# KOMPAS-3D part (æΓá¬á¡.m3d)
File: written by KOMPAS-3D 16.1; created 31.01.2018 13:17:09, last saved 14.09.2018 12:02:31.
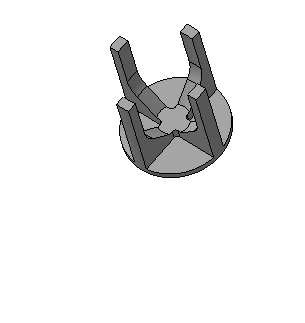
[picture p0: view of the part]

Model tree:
1. Эскиз:1
2. Операция вращения:1
     Угол 1 = 360
3. Эскиз:4
4. Операция выдавливания:3
     Расстояние 1 = 3.5; Расстояние 2 = 160
5. Эскиз:3
6. Вырезать элемент выдавливания:1
7. Массив по концентрической сетке:2  (with: Вырезать элемент выдавливания:1, Эскиз:3)  (4 pattern instances)
     Геометрический массив = 3; Шаг 2 = 360
8. Эскиз:5
9. Вырезать элемент выдавливания:2
     Расстояние 1 = 2
10. Фаска:1
     Угол = 45; Длина 1 = 1; Длина 2 = 1
11. Скругление:1
     Радиус = 15
12. Эскиз:8
13. Операция выдавливания:4
     Расстояние 1 = 10; Расстояние 2 = 6
14. Эскиз:9
15. Операция выдавливания:5
     Расстояние 1 = 3.5
16. Скругление:2
     Радиус = 2
17. Эскиз:7
18. Сечение поверхностью:1  (labels: А302-00.10.002 3Д)

Expressions: v184+10; 57.50+1-3
Referenced files in D:\МЭ200\Макеты\: Заготовка стакан.m3d
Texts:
  Линейный размер с обрывом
